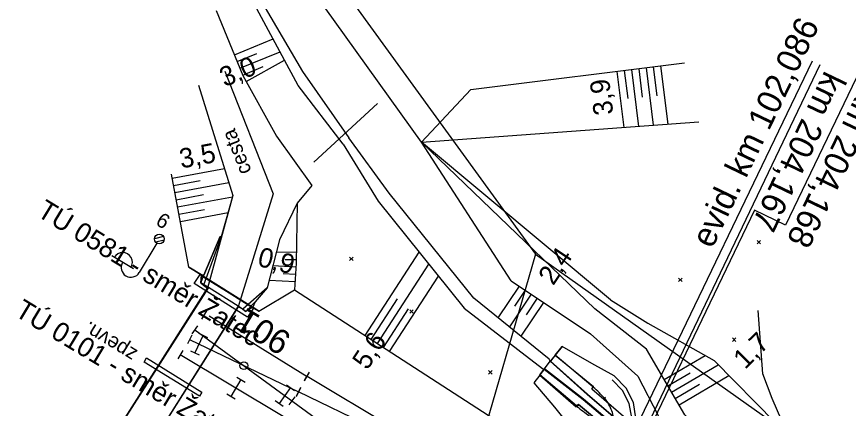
# Model space of a CAD drawing. Extents: x -800194 to -799078, y -1007177 to -1006597.
# Drawn here: x -799838.4 to -799753.2, y -1006953.5 to -1006913.4 of the extents above; entities that cross this region are included whole.
import ezdxf

# ---------------------------------------------------------------- set-up
doc = ezdxf.new("R2010")
doc.units = 0
for name, color, linetype in [('02_Osa_koleje', 7, 'Continuous'), ('_návrh', 7, 'Continuous'), ('Vrstva 16', 7, 'Continuous'), ('Vrstva 17', 7, 'Continuous'), ('Vrstva 18', 7, 'Continuous'), ('Vrstva 2', 7, 'Continuous'), ('Vrstva 25', 7, 'Continuous'), ('Vrstva 3', 7, 'Continuous'), ('Vrstva 45', 7, 'Continuous'), ('Vrstva 48', 7, 'Continuous'), ('Vrstva 49', 7, 'Continuous'), ('Vrstva 51', 7, 'Continuous'), ('Vrstva 55', 7, 'Continuous'), ('Vrstva 6', 7, 'Continuous')]:
    doc.layers.add(name, color=color, linetype=linetype)

msp = doc.modelspace()

# ---------------------------------------------------------------- linework, layer by layer
at = {"layer": '_návrh'}
for p, q in [((-799818.638, -1006944.048), (-799808.621, -1006950.252)), ((-799820.103, -1006945.483), (-799793.935, -1006964.581)), ((-799820.639, -1006946.461), (-799809.505, -1006951.835)), ((-799808.879, -1006950.668), (-799808.365, -1006949.81)), ((-799791.756, -1006960.321), (-799808.622, -1006950.239)), ((-799809.697, -1006952.286), (-799809.264, -1006951.385)), ((-799791.771, -1006960.349), (-799809.481, -1006951.835))]:
    msp.add_line(p, q, dxfattribs=at)
msp.add_lwpolyline([(-799821.595, -1006948.007), (-799811.064, -1006954.324), (-799803.753, -1006958.707), (-799793.935, -1006964.581), (-799784.224, -1006971.671), (-799782.913, -1006972.63), (-799767.418, -1006984.719), (-799752.333, -1006998.173), (-799735.027, -1007015.997), (-799721.623, -1007030.81), (-799713.555, -1007039.726), (-799713.111, -1007040.218)], dxfattribs=at)
at = {"layer": 'Vrstva 16'}
for p, q in [((-799783.217, -1006948.059), (-799782.509, -1006947.186)), ((-799783.233, -1006948.077), (-799783.722, -1006948.693)), ((-799784.321, -1006949.462), (-799784.796, -1006950.091)), ((-799784.321, -1006949.462), (-799783.722, -1006948.693)), ((-799784.795, -1006950.113), (-799785.4, -1006950.909)), ((-799778.158, -1006952.483), (-799777.802, -1006953.01))]:
    msp.add_line(p, q, dxfattribs=at)
for points in [[(-799785.4, -1006950.909), (-799783.301, -1006953.407), (-799781.69, -1006955.406), (-799780.41, -1006956.591), (-799778.888, -1006957.162), (-799777.239, -1006957.179), (-799775.528, -1006956.024), (-799774.978, -1006954.519), (-799775.211, -1006952.901), (-799775.953, -1006951.439), (-799777.187, -1006950.172), (-799779.455, -1006948.919), (-799782.509, -1006947.186)], [(-799819.635, -1006952.259), (-799825.306, -1006948.779), (-799825.052, -1006948.354), (-799819.395, -1006951.844), (-799819.635, -1006952.259)], [(-799783.233, -1006948.077), (-799783.708, -1006948.669), (-799783.722, -1006948.693)], [(-799779.465, -1006951.506), (-799779.351, -1006951.322), (-799783.233, -1006948.077), (-799783.217, -1006948.059), (-799779.283, -1006951.287)], [(-799784.796, -1006950.091), (-799784.356, -1006949.5), (-799784.321, -1006949.462)], [(-799727.258, -1006999.988), (-799736.887, -1006992.032), (-799742.859, -1006987.132), (-799754.894, -1006975.337), (-799764.135, -1006966.374), (-799777.698, -1006954.783), (-799780.331, -1006952.581), (-799784.321, -1006949.462)], [(-799726.857, -1006999.659), (-799736.574, -1006991.623), (-799742.439, -1006986.725), (-799754.518, -1006974.879), (-799763.734, -1006965.993), (-799777.293, -1006954.374), (-799779.945, -1006952.099), (-799783.722, -1006948.693)], [(-799783.708, -1006948.669), (-799779.9, -1006952.065), (-799777.252, -1006954.333), (-799763.672, -1006965.935), (-799754.476, -1006974.829), (-799742.393, -1006986.703), (-799736.524, -1006991.578), (-799726.778, -1006999.642)], [(-799780.843, -1006953.125), (-799781.023, -1006953.264), (-799784.796, -1006950.091)], [(-799784.796, -1006950.091), (-799784.795, -1006950.113), (-799781.066, -1006953.365)], [(-799784.356, -1006949.5), (-799780.347, -1006952.62), (-799777.716, -1006954.827), (-799764.168, -1006966.436), (-799754.935, -1006975.363), (-799742.857, -1006987.188), (-799736.94, -1006992.081), (-799727.324, -1007000.028)], [(-799779.465, -1006951.506), (-799778.251, -1006952.583), (-799776.738, -1006953.884), (-799763.224, -1006965.504), (-799753.999, -1006974.421), (-799741.964, -1006986.204), (-799736.168, -1006991.012), (-799728.577, -1006997.215), (-799726.123, -1006999.163)], [(-799779.316, -1006951.352), (-799779.283, -1006951.287), (-799779.351, -1006951.322)], [(-799780.997, -1006953.316), (-799781.066, -1006953.365), (-799781.023, -1006953.264)], [(-799727.952, -1007000.326), (-799729.82, -1006998.717), (-799737.37, -1006992.486), (-799743.358, -1006987.594), (-799755.401, -1006975.883), (-799764.592, -1006966.926), (-799778.073, -1006955.449), (-799779.598, -1006954.142), (-799780.843, -1006953.125)]]:
    msp.add_lwpolyline(points, dxfattribs=at)
for centre, major_axis, ratio, start_param, end_param in [((-799780.763, -1006952.85), (1.448, 1.499), 0.000154, 0.037167, 0.458976), ((-799789.88, -1006959.484), (14.602, -0.402), 0.815768, 0.661553, 0.784611), ((-799779.38, -1006951.872), (-1.627, -1.481), 0.054497, 5.778056, 6.111601), ((-799765.39, -1006947.43), (22.33, -7.783), 0.537883, 4.140419, 4.216217), ((-799780.886, -1006955.173), (2.894, 2.414), 0.919745, 5.794757, 6.192371)]:
    msp.add_ellipse(centre, major_axis=major_axis, ratio=ratio, start_param=start_param, end_param=end_param, dxfattribs=at)
at = {"layer": 'Vrstva 17'}
msp.add_line((-799814.29, -1006943.164), (-799819.456, -1006939.933), dxfattribs=at)
for points in [[(-799756.721, -1006963.941), (-799759.125, -1006956.836), (-799761.008, -1006952.49), (-799761.962, -1006949.962), (-799762.434, -1006943.507)], [(-799781.343, -1006955.343), (-799780.121, -1006956.276), (-799778.697, -1006956.784), (-799777.217, -1006956.75), (-799775.995, -1006955.84), (-799775.356, -1006954.486), (-799775.648, -1006953.011), (-799776.321, -1006951.673), (-799777.368, -1006950.593)]]:
    msp.add_lwpolyline(points, dxfattribs=at)
at = {"layer": 'Vrstva 18'}
for p, q in [((-799819.421, -1006939.843), (-799819.489, -1006940.661)), ((-799819.489, -1006940.661), (-799819.417, -1006939.849)), ((-799829.152, -1006957.479), (-799818.799, -1006941.218)), ((-799818.724, -1006941.148), (-799829.145, -1006957.469)), ((-799815.675, -1006943.054), (-799818.724, -1006941.148)), ((-799826.019, -1006959.481), (-799815.665, -1006943.128)), ((-799815.675, -1006943.054), (-799826.005, -1006959.461)), ((-799815.184, -1006943.369), (-799814.895, -1006943.587)), ((-799814.201, -1006943.118), (-799814.895, -1006943.587)), ((-799814.184, -1006943.153), (-799814.895, -1006943.587)), ((-799778.158, -1006952.483), (-799777.802, -1006953.01))]:
    msp.add_line(p, q, dxfattribs=at)
for points in [[(-799817.501, -1006935.902), (-799817.4, -1006935.944), (-799819.236, -1006940.912), (-799818.799, -1006941.218), (-799818.724, -1006941.148), (-799819.489, -1006940.661), (-799819.236, -1006940.912)], [(-799819.489, -1006940.661), (-799819.173, -1006939.861), (-799817.501, -1006935.902)], [(-799819.557, -1006939.811), (-799820.713, -1006939.059), (-799819.421, -1006939.843), (-799819.417, -1006939.849), (-799814.201, -1006943.118)], [(-799814.11, -1006943.242), (-799814.704, -1006944.176), (-799820.193, -1006940.743), (-799819.557, -1006939.811), (-799814.11, -1006943.242)], [(-799812.688, -1006941.178), (-799813.94, -1006942.608), (-799814.895, -1006943.587), (-799815.675, -1006943.054)], [(-799812.688, -1006941.178), (-799815.184, -1006943.369), (-799815.665, -1006943.128), (-799815.675, -1006943.054)], [(-799814.11, -1006943.242), (-799813.557, -1006943.557), (-799813.557, -1006943.559), (-799814.184, -1006943.153), (-799814.201, -1006943.118)], [(-799779.465, -1006951.506), (-799778.251, -1006952.583), (-799776.738, -1006953.884)], [(-799780.843, -1006953.125), (-799779.598, -1006954.142), (-799778.073, -1006955.449)]]:
    msp.add_lwpolyline(points, dxfattribs=at)
for centre, major_axis, ratio, start_param, end_param in [((-799780.763, -1006952.85), (1.448, 1.499), 0.000154, 0.037167, 0.458976), ((-799789.88, -1006959.484), (14.602, -0.402), 0.815768, 0.661553, 0.784611), ((-799779.129, -1006954.252), (1.075, 1.846), 0.080877, 0.165328, 0.490733), ((-799779.092, -1006953.855), (1.015, 1.471), 0.015652, 6.081072, 6.66336), ((-799779.38, -1006951.872), (-1.627, -1.481), 0.054497, 5.778056, 6.111601), ((-799765.39, -1006947.43), (22.33, -7.783), 0.537883, 4.140419, 4.216217), ((-799780.886, -1006955.173), (2.894, 2.414), 0.919745, 5.794757, 6.192371)]:
    msp.add_ellipse(centre, major_axis=major_axis, ratio=ratio, start_param=start_param, end_param=end_param, dxfattribs=at)
at = {"layer": 'Vrstva 2'}
for p, q in [((-799756.904, -1006917.966), (-799780.025, -1006965.993)), ((-799819.384, -1006944.384), (-799818.87, -1006943.526)), ((-799820.398, -1006945.887), (-799819.808, -1006945.079)), ((-799820.421, -1006946.011), (-799820.857, -1006946.911)), ((-799821.338, -1006947.578), (-799821.852, -1006948.436)), ((-799808.877, -1006950.681), (-799808.365, -1006949.823)), ((-799809.289, -1006951.384), (-799809.721, -1006952.286)), ((-799810.438, -1006953.151), (-799809.848, -1006952.343))]:
    msp.add_line(p, q, dxfattribs=at)
msp.add_circle((-799815.088, -1006949.141), 0.4, dxfattribs=at)
at = {"layer": 'Vrstva 25'}
for p, q in [((-799823.993, -1006936.599), (-799825.792, -1006939.601)), ((-799823.306, -1006935.918), (-799824.235, -1006936.151)), ((-799823.251, -1006936.29), (-799824.104, -1006936.504)), ((-799826.392, -1006939.242), (-799828.623, -1006937.905))]:
    msp.add_line(p, q, dxfattribs=at)
msp.add_circle((-799823.736, -1006936.17), 0.5, dxfattribs=at)
for centre, start, end in [((-799827.501, -1006938.563), 328.37187, 149.77701), ((-799826.65, -1006939.087), 149.07444, 329.07444)]:
    msp.add_arc(centre, 1, start, end, dxfattribs=at)
at = {"layer": 'Vrstva 3'}
for p, q in [((-799756.121, -1006918.343), (-799779.128, -1006966.408)), ((-799819.246, -1006946.024), (-799820.116, -1006947.826)), ((-799819.697, -1006945.807), (-799818.796, -1006946.242)), ((-799820.566, -1006947.608), (-799819.665, -1006948.043)), ((-799815.817, -1006950.316), (-799814.96, -1006950.832)), ((-799815.388, -1006950.574), (-799816.42, -1006952.288)), ((-799810.708, -1006951.098), (-799809.9, -1006951.688)), ((-799816.848, -1006952.03), (-799815.991, -1006952.546)), ((-799810.304, -1006951.393), (-799811.482, -1006953.009)), ((-799811.886, -1006952.714), (-799811.078, -1006953.304))]:
    msp.add_line(p, q, dxfattribs=at)
at = {"layer": 'Vrstva 45'}
msp.add_line((-799807.917, -1006928.309), (-799801.411, -1006922.31), dxfattribs=at)
at = {"layer": 'Vrstva 48'}
for p, q in [((-799816.059, -1006917.301), (-799812.099, -1006915.664)), ((-799815.486, -1006918.687), (-799811.385, -1006916.992)), ((-799815.773, -1006917.994), (-799813.758, -1006917.161)), ((-799814.84, -1006920.039), (-799810.913, -1006917.871)), ((-799815.2, -1006919.38), (-799813.114, -1006918.518)), ((-799775.409, -1006918.818), (-799774.69, -1006924.632)), ((-799774.665, -1006918.726), (-799774.303, -1006921.651)), ((-799773.92, -1006918.633), (-799773.192, -1006924.523)), ((-799773.176, -1006918.541), (-799772.809, -1006921.505)), ((-799772.432, -1006918.449), (-799771.694, -1006924.413)), ((-799776.898, -1006919.002), (-799776.188, -1006924.741)), ((-799776.153, -1006918.91), (-799775.796, -1006921.798)), ((-799822.421, -1006929.94), (-799817.083, -1006928.94)), ((-799822.283, -1006930.677), (-799819.571, -1006930.169)), ((-799822.145, -1006931.414), (-799816.636, -1006930.382)), ((-799822.007, -1006932.151), (-799819.21, -1006931.627)), ((-799821.869, -1006932.888), (-799816.26, -1006931.838)), ((-799821.73, -1006933.625), (-799819.107, -1006933.134)), ((-799821.592, -1006934.363), (-799816.707, -1006933.448)), ((-799809.72, -1006937.564), (-799811.768, -1006937.523)), ((-799802.684, -1006946.043), (-799797.153, -1006937.521)), ((-799809.735, -1006938.314), (-799810.845, -1006938.292)), ((-799809.766, -1006939.063), (-799812.122, -1006938.929)), ((-799801.425, -1006946.86), (-799796.163, -1006938.751)), ((-799809.808, -1006939.812), (-799811.058, -1006939.741)), ((-799800.167, -1006947.676), (-799795.173, -1006939.98)), ((-799809.85, -1006940.56), (-799812.495, -1006940.41)), ((-799786.921, -1006940.996), (-799789.081, -1006944.231)), ((-799786.297, -1006941.412), (-799787.396, -1006943.059)), ((-799802.054, -1006946.452), (-799799.356, -1006942.294)), ((-799785.673, -1006941.829), (-799787.91, -1006945.178)), ((-799784.426, -1006942.662), (-799786.738, -1006946.125)), ((-799785.05, -1006942.245), (-799786.187, -1006943.948)), ((-799800.796, -1006947.268), (-799798.232, -1006943.317)), ((-799772.055, -1006950.547), (-799767.867, -1006948.1)), ((-799771.298, -1006951.842), (-799766.522, -1006949.052)), ((-799771.676, -1006951.195), (-799769.393, -1006949.861)), ((-799770.541, -1006953.137), (-799765.435, -1006950.154)), ((-799770.919, -1006952.49), (-799768.449, -1006951.046))]:
    msp.add_line(p, q, dxfattribs=at)
at = {"layer": 'Vrstva 49'}
for p, q in [((-799796.895, -1006926.253), (-799768.526, -1006924.182)), ((-799787.714, -1006940.466), (-799796.895, -1006926.253)), ((-799777.554, -1006942.387), (-799796.895, -1006926.253)), ((-799809.62, -1006932.499), (-799811.447, -1006936.25)), ((-799762.55, -1006936.32), (-799762.196, -1006936.674)), ((-799762.55, -1006936.674), (-799762.196, -1006936.32)), ((-799804.269, -1006938.024), (-799803.915, -1006938.378)), ((-799804.269, -1006938.378), (-799803.915, -1006938.024)), ((-799770.589, -1006940.179), (-799770.235, -1006940.533)), ((-799770.589, -1006940.533), (-799770.235, -1006940.179)), ((-799813.557, -1006943.557), (-799809.896, -1006941.363)), ((-799798.109, -1006943.418), (-799797.755, -1006943.772)), ((-799798.109, -1006943.772), (-799797.755, -1006943.418)), ((-799765.068, -1006946.299), (-799764.714, -1006946.653)), ((-799765.068, -1006946.653), (-799764.714, -1006946.299)), ((-799790.032, -1006949.644), (-799789.678, -1006949.998)), ((-799790.032, -1006949.998), (-799789.678, -1006949.644))]:
    msp.add_line(p, q, dxfattribs=at)
for points in [[(-799779.16, -1006943.327), (-799796.895, -1006926.253), (-799814.584, -1006901.56)], [(-799816.484, -1006906.344), (-799809.08, -1006919.031), (-799804.329, -1006925.793)], [(-799804.932, -1006926.453), (-799809.531, -1006920.441), (-799816.788, -1006906.944)], [(-799817.932, -1006912.771), (-799815.187, -1006919.411), (-799811.746, -1006925.644), (-799808.124, -1006930.682), (-799809.62, -1006932.499), (-799809.741, -1006938.631), (-799809.896, -1006941.363)], [(-799796.895, -1006926.253), (-799791.85, -1006920.852), (-799769.973, -1006918.145)], [(-799819.72, -1006920.416), (-799816.225, -1006931.712), (-799817.4, -1006935.944), (-799817.501, -1006935.902), (-799819.173, -1006939.861), (-799819.421, -1006939.843), (-799820.713, -1006939.059)], [(-799804.932, -1006926.453), (-799801.356, -1006932.305), (-799792.538, -1006943.25), (-799784.51, -1006949.428)], [(-799783.829, -1006948.476), (-799791.557, -1006942.231), (-799800.207, -1006931.486), (-799804.329, -1006925.793)], [(-799820.713, -1006939.059), (-799822.5, -1006929.516)], [(-799811.447, -1006936.25), (-799812.688, -1006941.178), (-799813.94, -1006942.608), (-799814.184, -1006943.153), (-799813.557, -1006943.559), (-799813.557, -1006943.557)], [(-799787.714, -1006940.466), (-799779.601, -1006945.884), (-799774.772, -1006950.23), (-799772.678, -1006954.259), (-799772.914, -1006957.256), (-799775.374, -1006960.084), (-799777.823, -1006961.225), (-799780.709, -1006960.303)], [(-799809.896, -1006941.363), (-799780.709, -1006960.303)], [(-799777.554, -1006942.387), (-799773.745, -1006944.786), (-799766.953, -1006948.615), (-799760.613, -1006955.042), (-799758.076, -1006961.72), (-799756.886, -1006965.592)], [(-799760.173, -1006964.364), (-799762.769, -1006960.758), (-799769.93, -1006954.183), (-799773.856, -1006947.464), (-799779.16, -1006943.327)], [(-799784.51, -1006949.428), (-799784.321, -1006949.462), (-799784.796, -1006950.091), (-799784.795, -1006950.113), (-799785.4, -1006950.909), (-799783.301, -1006953.407), (-799781.69, -1006955.406), (-799780.41, -1006956.591), (-799778.888, -1006957.162), (-799777.239, -1006957.179), (-799775.528, -1006956.024), (-799774.978, -1006954.519), (-799775.211, -1006952.901), (-799775.953, -1006951.439), (-799777.187, -1006950.172), (-799779.455, -1006948.919), (-799782.509, -1006947.186), (-799783.217, -1006948.059), (-799783.233, -1006948.077), (-799783.722, -1006948.693), (-799783.829, -1006948.476)]]:
    msp.add_lwpolyline(points, dxfattribs=at)
at = {"layer": 'Vrstva 51'}
for points in [[(-799817.051, -1006918.973), (-799812.091, -1006931.542), (-799815.665, -1006943.128), (-799826.019, -1006959.481), (-799831.215, -1006965.513), (-799832.478, -1006972.309), (-799831.126, -1006986.858), (-799828.082, -1006983.271), (-799821.896, -1006976.034), (-799813.152, -1006974.923), (-799805.94, -1006982.791), (-799808.362, -1006984.771), (-799815.088, -1006977.554), (-799820.319, -1006978.428), (-799823.433, -1006985.376), (-799830.084, -1006997.726), (-799819.519, -1007011.695), (-799817.354, -1007013.08), (-799784.788, -1007044.956), (-799778.171, -1007047.694), (-799743.858, -1007056.783), (-799726.629, -1007061.89)], [(-799819.72, -1006920.416), (-799816.225, -1006931.712), (-799818.799, -1006941.218), (-799829.152, -1006957.479), (-799833.813, -1006964.907), (-799834.878, -1006971.883), (-799834.851, -1006980.391), (-799838.352, -1006981.216)]]:
    msp.add_lwpolyline(points, dxfattribs=at)
at = {"layer": 'Vrstva 55'}
msp.add_line((-799785.23, -1006937.71), (-799741.57, -1006968.68), dxfattribs=at)
for points in [[(-799815.49, -1006895.78), (-799807.53, -1006905.17), (-799803.4, -1006912.69), (-799785.23, -1006937.71)], [(-799785.23, -1006937.71), (-799791.69, -1006959.99), (-799791.97, -1006960.97), (-799746.76, -1006987.67), (-799745.68, -1006988.03), (-799733.28, -1006992.13)]]:
    msp.add_lwpolyline(points, dxfattribs=at)
at = {"layer": 'Vrstva 6'}
msp.add_lwpolyline([(-799752.416, -1006919.71), (-799759.639, -1006934.751), (-799762.823, -1006933.223), (-799777.74, -1006964.286)], dxfattribs=at)

# ---------------------------------------------------------------- texts
at = {"layer": '02_Osa_koleje'}
for s, rotation, p in [('TÚ 0581 - směr Žatec', 328.68017, (-799836.385, -1006933.748)), ('TÚ 0101 - směr Žatec', 328.93903, (-799838.658, -1006943.961))]:
    msp.add_text(s, height=2, rotation=rotation, dxfattribs=at).set_placement(p)
at = {"layer": 'Vrstva 16'}
msp.add_text('zpevn.', height=1.5, rotation=148.46471, dxfattribs=at).set_placement((-799825.888, -1006947.616))
at = {"layer": 'Vrstva 2'}
for s, rotation, p in [('evid. km 102,086', 64.34886, (-799767.141, -1006937.24)), ('901', 149.06272, (-799810.068, -1006946.029))]:
    msp.add_text(s, height=2.5, rotation=rotation, dxfattribs=at).set_placement(p)
at = {"layer": 'Vrstva 25'}
msp.add_text('9', height=1.5, rotation=149.07444, dxfattribs=at).set_placement((-799822.483, -1006933.94))
at = {"layer": 'Vrstva 3'}
msp.add_text('km 204,167', height=2.5, rotation=244.42082, dxfattribs=at).set_placement((-799755.61, -1006918.831))
at = {"layer": 'Vrstva 48'}
for s, rotation, p in [('3,0', 22.46038, (-799817.059, -1006920.634)), ('3,9', 97.05377, (-799777.256, -1006923.37)), ('3,5', 10.60624, (-799821.497, -1006928.955)), ('0,9', 345.86531, (-799813.791, -1006938.9)), ('2,4', 56.26432, (-799783.421, -1006941.016)), ('5,6', 57.01969, (-799802.446, -1006949.672)), ('1,7', 44.60957, (-799763.776, -1006949.581))]:
    msp.add_text(s, height=2, rotation=rotation, dxfattribs=at).set_placement(p)
at = {"layer": 'Vrstva 51'}
msp.add_text('cesta', height=1.5, rotation=111.53527, dxfattribs=at).set_placement((-799814.275, -1006929.223))
at = {"layer": 'Vrstva 6'}
msp.add_text('km 204,168', height=2.5, rotation=244.34847, dxfattribs=at).set_placement((-799752.001, -1006920.52))

doc.saveas('drawing.dxf')
